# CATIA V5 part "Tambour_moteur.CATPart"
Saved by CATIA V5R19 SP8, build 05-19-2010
Part number: Tambour_moteur
Nomenclature: 39_a
Material "Acier": density 7860 kg/m3, Young's modulus 2e+11 Pa, Poisson ratio 0.266, thermal expansion 1.17e-05 1/K
Material "Plastique": density 1200 kg/m3, Young's modulus 2.2e+09 Pa, Poisson ratio 0.38, thermal expansion 6.84e-05 1/K
Bounding box of the stored display mesh (mm): x -250 to 250.1, y -40 to 40, z -39.996 to 39.996
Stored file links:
  C:\Users\rphgr\Desktop\0_Tapis_TC520B_vitesse\Tambour_moteur.CATPart
  D:\Programmes\DassaultSysteme\win_b64\startup\materials\French\Catalog.CATMaterial
  D:\Documents\1_Travail\1 - ac-limoges.fr\ac-limoges.fr\Emmanuel Maynard - STI2D_Turgot\3 - Supports\Tapis de course TC520B\Tapis de course TC520B_Ca\Poulie_inertie.CATPart
  D:\Documents\1_Travail\1 - ac-limoges.fr\ac-limoges.fr\Emmanuel Maynard - STI2D_Turgot\3 - Supports\Tapis de course TC520B\Tapis de course TC520B_Ca\0_Tapis_TC520B.CATProduct
  D:\Documents\1_Travail\1 - ac-limoges.fr\ac-limoges.fr\Emmanuel Maynard - STI2D_Turgot\3 - Supports\Tapis de course TC520B\Tapis de course TC520B_Ca\Tapis.CATPart
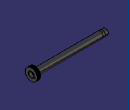
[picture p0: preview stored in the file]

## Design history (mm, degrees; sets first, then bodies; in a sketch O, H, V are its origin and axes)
AxisSystem1: origin (0, 0, 0), X (1, 0, 0), Y (0, 1, 0), Z (0, 0, 1)
Set1
  Plane1: linked copy from another document
Set2
  Sketch1 on Plane1, origin (-12.5, 0, 0), H (0, 1, 0), V (0, 0, 1)
    projected circle E1 centre (0, 0) radius 21 from edge [face of Shaft1 | face of Shaft1]
Body1 (main body), material "Acier"
  Sketch2 on ZX plane of AxisSystem1, origin (0, 0, 0), H (0, 0, 1), V (1, 0, 0)
    axis line L1 (0, -425) -> (0, 345.5398)
    point P1 (0, -425)
    point P3 (21, 0)
    line L2 (21, 0) -> (21, -215)
    point P4 (21, -215)
    line L3 (21, -215) -> (19.5, -230)
    line L4 (19.5, -230) -> (19.5, -250)
    point P6 (19.5, -250)
    distance L4 L1 = 19.5
    distance L2 L1 = 21
    distance P6 H = 250
    length L4 = 20
    distance P4 P6 V = 35
    coincidence: P1 V, L3 P1, P3 H
    vertical: L1 V, L2 V, L4 V
  Shaft1: profile Sketch2, axis Sketch2.L1, angle 360, thin wall 0, second thickness 2
  Mirror1: of the body so far, about face of Shaft1
Body2 "Poulie", material "Plastique"
  Sketch3 on face of Mirror1, origin (250, 0, 0), H (0, 1, 0), V (0, 0, 1)
    circle A1 centre (0, 0) radius 40
    projected circle E1 centre (0, 0) radius 19.5 from edge [face of Mirror1 | face of Mirror1]
    radius A1 = 40
  Pad1: profile Sketch3, direction (-1, 0, 0), length 23
  Sketch4 on ZX plane of AxisSystem1, origin (0, 0, 0), H (0, 0, 1), V (1, 0, 0)
    line L1 (39.9342, 231.386) -> (37.4942, 230.4979)
    line L2 (37.4942, 230.1221) -> (39.9342, 229.234)
    line L3 (40, 231.48) -> (40, 229.14)
    arc A1 centre (39.9, 229.14) radius 0.1 from (39.9342, 229.234) to (40, 229.14) cw
    arc A2 centre (39.9, 231.48) radius 0.1 from (39.9342, 231.386) to (40, 231.48) ccw
    point P5 (40, 229.14)
    point P6 (40, 231.48)
    arc A3 centre (37.5626, 230.31) radius 0.2 from (37.4942, 230.4979) to (37.4942, 230.1221) ccw
    reference intersected line E1 through (0, 227) direction (-1, 0) from end face of Pad1
    radius A1 = 0.1
    radius A2 = 0.1
    radius A3 = 0.2
    angle L1 L3 = 70
    distance P6 P5 = 2.34
    distance P5 E1 = 2.14
    angle L1 L2 = 40
    vertical: L3 V
    tangency: A1 L2, A1 L3, A2 L1, A2 L3, A3 L1, A3 L2
  Groove1: profile Sketch4, axis axis of face of Pad1 from Sketch3.A1, angle 360
  RectPattern1: of Groove1, direction 1 instances 8, spacing 2.34, along axis of face of Pad1 from Sketch3.A1
  Sketch5 on start face of Pad1, origin (250, 0, 0), H (0, 1, 0), V (0, 0, 1)
    circle A1 centre (24.7655, -10.1506) radius 3.3695
  Pad2: profile Sketch5, direction (1, 0, 0), length 0.1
